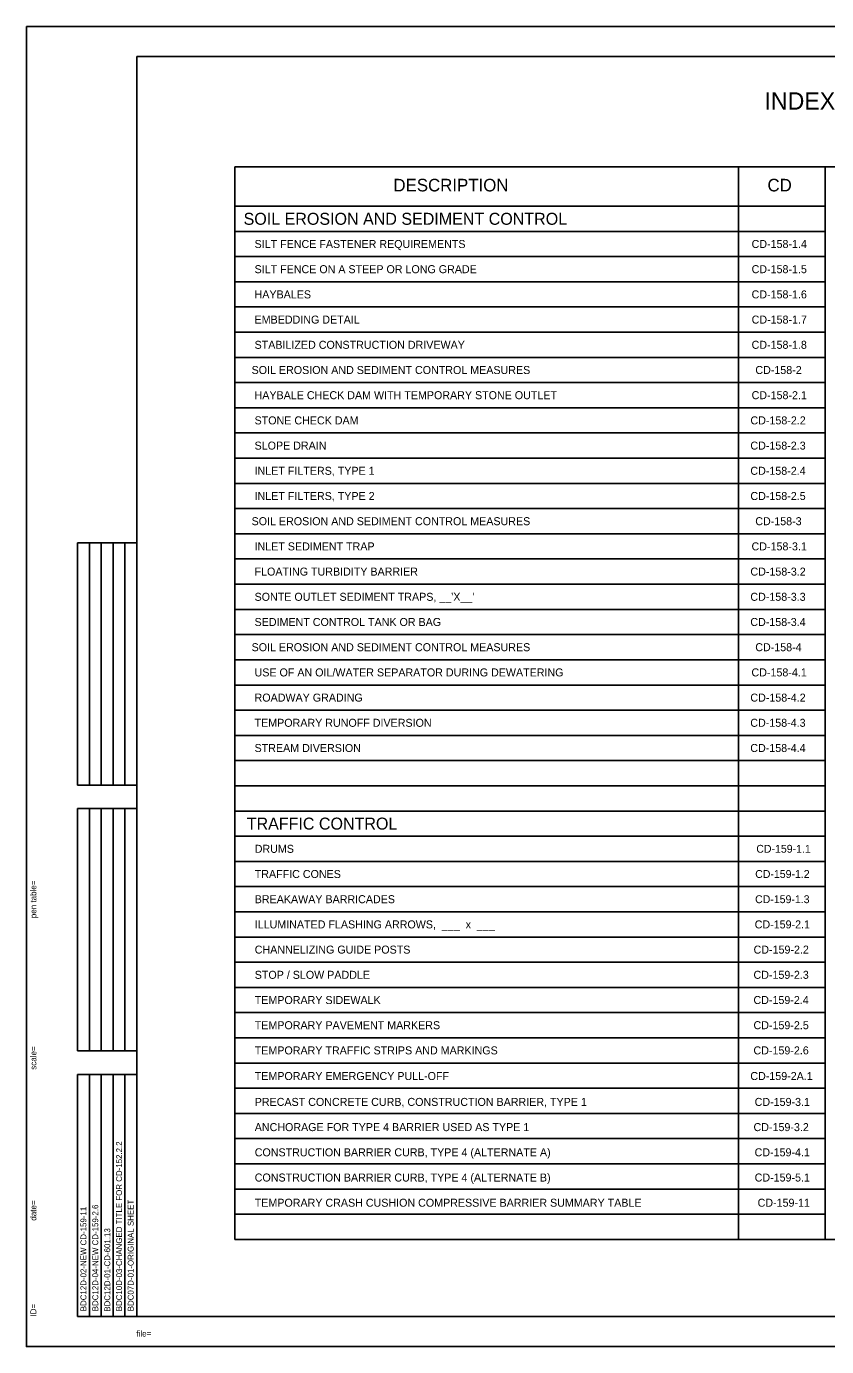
# Model space of a CAD drawing. Extents: x 503613 to 504661, y 499104 to 499764.
# Drawn here: x 503613 to 504013, y 499104 to 499764 of the extents above; entities that cross this region are included whole.
import ezdxf

# ---------------------------------------------------------------- set-up
doc = ezdxf.new("R2010")
doc.units = 0
for name, color, linetype in [('1', 7, 'Continuous'), ('39', 7, 'Continuous'), ('41', 7, 'Continuous')]:
    doc.layers.add(name, color=color, linetype=linetype)

msp = doc.modelspace()

# ---------------------------------------------------------------- linework, layer by layer
at = {"layer": '1'}
for p, q in [((504661.22, 499764.48), (503613.04, 499764.48)), ((504658.22, 499749.48), (503668.22, 499749.48)), ((503668.22, 499749.48), (503668.22, 499119.48)), ((503717.27, 499694.28), (504603.1, 499694.28)), ((503717.27, 499158.06), (503717.27, 499694.28)), ((503717.27, 499674.59), (503717.27, 499694.28)), ((503969.24, 499158.06), (503969.24, 499694.28)), ((503969.24, 499674.59), (503969.24, 499694.28)), ((504012.55, 499158.06), (504012.55, 499694.28)), ((504012.55, 499674.59), (504012.55, 499694.28)), ((503717.27, 499674.59), (504012.55, 499674.59)), ((503717.27, 499662), (504012.55, 499662)), ((503717.27, 499649.4), (504012.55, 499649.4)), ((503717.27, 499636.8), (504012.55, 499636.8)), ((503717.27, 499624.2), (504012.55, 499624.2)), ((503717.27, 499611.6), (504012.55, 499611.6)), ((503717.27, 499599), (504012.55, 499599)), ((503717.27, 499586.41), (504012.55, 499586.41)), ((503717.27, 499573.81), (504012.55, 499573.81)), ((503717.27, 499561.21), (504012.55, 499561.21)), ((503717.27, 499548.61), (504012.55, 499548.61)), ((503717.27, 499536.01), (504012.55, 499536.01)), ((503717.27, 499523.41), (504012.55, 499523.41)), ((503717.27, 499510.82), (504012.55, 499510.82)), ((503638.69, 499506.29), (503668.22, 499506.29)), ((503638.69, 499385.22), (503638.69, 499506.29)), ((503644.59, 499385.22), (503644.59, 499506.29)), ((503650.5, 499385.22), (503650.5, 499506.29)), ((503656.41, 499385.22), (503656.41, 499506.29)), ((503662.31, 499385.22), (503662.31, 499506.29)), ((503717.27, 499498.22), (504012.55, 499498.22)), ((503717.27, 499485.62), (504012.55, 499485.62)), ((503717.27, 499473.02), (504012.55, 499473.02)), ((503717.27, 499460.42), (504012.55, 499460.42)), ((503717.27, 499447.82), (504012.55, 499447.82)), ((503717.27, 499435.22), (504012.55, 499435.22)), ((503717.27, 499422.63), (504012.55, 499422.63)), ((503717.27, 499410.03), (504012.55, 499410.03)), ((503717.27, 499397.43), (504012.55, 499397.43)), ((503668.22, 499385.22), (503638.69, 499385.22)), ((503717.27, 499384.83), (504012.55, 499384.83)), ((503638.69, 499373.41), (503668.22, 499373.41)), ((503638.69, 499252.35), (503638.69, 499373.41)), ((503644.59, 499252.35), (503644.59, 499373.41)), ((503650.5, 499252.35), (503650.5, 499373.41)), ((503656.41, 499252.35), (503656.41, 499373.41)), ((503662.31, 499252.35), (503662.31, 499373.41)), ((503717.27, 499372.23), (504012.55, 499372.23)), ((503717.27, 499359.63), (504012.55, 499359.63)), ((503717.27, 499347.04), (504012.55, 499347.04)), ((503717.27, 499334.44), (504012.55, 499334.44)), ((503717.27, 499321.84), (504012.55, 499321.84)), ((503717.27, 499309.24), (504012.55, 499309.24)), ((503717.27, 499296.64), (504012.55, 499296.64)), ((503717.27, 499284.04), (504012.55, 499284.04)), ((503717.27, 499271.44), (504012.55, 499271.44)), ((503717.27, 499258.85), (504012.55, 499258.85)), ((503668.22, 499252.35), (503638.69, 499252.35)), ((503717.27, 499246.25), (504012.55, 499246.25)), ((503638.69, 499119.48), (503638.69, 499240.54)), ((503638.69, 499240.54), (503668.22, 499240.54)), ((503644.59, 499119.48), (503644.59, 499240.54)), ((503650.5, 499119.48), (503650.5, 499240.54)), ((503656.41, 499119.48), (503656.41, 499240.54)), ((503662.31, 499119.48), (503662.31, 499240.54)), ((503717.27, 499233.65), (504012.55, 499233.65)), ((503717.27, 499221.05), (504012.55, 499221.05)), ((503717.27, 499208.45), (504012.55, 499208.45)), ((503717.27, 499195.85), (504012.55, 499195.85)), ((503717.27, 499183.26), (504012.55, 499183.26)), ((503717.27, 499170.66), (504012.55, 499170.66)), ((503717.27, 499158.06), (504603.1, 499158.06)), ((503717.27, 499158.06), (504012.55, 499158.06)), ((503668.22, 499119.48), (503638.69, 499119.48)), ((503668.22, 499119.48), (504658.22, 499119.48)), ((504661.22, 499104.48), (503613.04, 499104.48))]:
    msp.add_line(p, q, dxfattribs=at)
at = {"layer": '41'}
msp.add_lwpolyline([(503613.04, 499764.48), (504661.22, 499764.48), (504661.22, 499104.48), (503613.04, 499104.48)], close=True, dxfattribs=at)

# ---------------------------------------------------------------- texts
at = {"layer": '1'}
for s, height, p in [('DESCRIPTION', 6.2992, (503796.64, 499681.98)), ('CD', 6.299, (503983.75, 499681.98))]:
    msp.add_text(s, height=height, dxfattribs=at).set_placement(p)
for s, height, rotation, p in [('...................pentable..................', 0.0432, 90, (503618.04, 499342.54)), ('pen table=', 3, 90, (503618.04, 499318.64)), ('......scale......', 0.0432, 90, (503618.04, 499257.54)), ('scale=', 3, 90, (503618.04, 499242.87)), ('.......time......', 0.0432, 90, (503618.04, 499180.54)), ('date=', 3, 90, (503618.04, 499167.41)), ('ID=', 3, 90, (503618.04, 499119.5)), ('............who............', 0.0432, 90, (503618.04, 499127.48)), ('file=', 3, 360, (503668.05, 499109.48)), ('...................bob..................', 0.0432, 360, (503678.04, 499109.48))]:
    msp.add_text(s, height=height, rotation=rotation, dxfattribs=at).set_placement(p)
at = {"layer": '39'}
for s, height, p in [('INDEX FOR STANDARD ROADWAY CONSTRUCTION DETAILS', 8.6614, (503982.24, 499722.87)), ('SOIL EROSION AND SEDIMENT CONTROL ', 6, (503721.7, 499665.29)), (' SILT FENCE FASTENER REQUIREMENTS', 4, (503725.7, 499653.7)), ('CD-158-1.4', 4, (503975.81, 499653.7)), (' SILT FENCE ON A STEEP OR LONG GRADE', 4, (503725.7, 499641.1)), ('CD-158-1.5', 4, (503975.81, 499641.1)), (' HAYBALES', 4, (503725.7, 499628.5)), ('CD-158-1.6', 4, (503975.81, 499628.5)), (' EMBEDDING DETAIL', 4, (503725.7, 499615.9)), ('CD-158-1.7', 4, (503975.83, 499615.9)), (' STABILIZED CONSTRUCTION DRIVEWAY', 4, (503725.7, 499603.3)), ('CD-158-1.8', 4, (503975.81, 499603.3)), ('SOIL EROSION AND SEDIMENT CONTROL MEASURES', 4, (503725.7, 499590.7)), ('CD-158-2', 4, (503977.69, 499590.7)), (' HAYBALE CHECK DAM WITH TEMPORARY STONE OUTLET', 4, (503725.7, 499578.11)), ('CD-158-2.1', 4, (503975.81, 499578.11)), (' STONE CHECK DAM', 4, (503725.7, 499565.51)), ('CD-158-2.2', 4, (503975.24, 499565.51)), (' SLOPE DRAIN', 4, (503725.7, 499552.91)), ('CD-158-2.3', 4, (503975.21, 499552.91)), (' INLET FILTERS, TYPE 1', 4, (503725.7, 499540.31)), ('CD-158-2.4', 4, (503975.2, 499540.31)), (' INLET FILTERS, TYPE 2', 4, (503725.7, 499527.71)), ('CD-158-2.5', 4, (503975.21, 499527.71)), ('SOIL EROSION AND SEDIMENT CONTROL MEASURES', 4, (503725.7, 499515.11)), ('CD-158-3', 4, (503977.65, 499515.11)), (' INLET SEDIMENT TRAP', 4, (503725.7, 499502.52)), ('CD-158-3.1', 4, (503975.79, 499502.52)), (' FLOATING TURBIDITY BARRIER', 4, (503725.7, 499489.92)), ('CD-158-3.2', 4, (503975.22, 499489.92)), (" SONTE OUTLET SEDIMENT TRAPS, __'X__'", 4, (503725.7, 499477.32)), ('CD-158-3.3', 4, (503975.19, 499477.32)), (' SEDIMENT CONTROL TANK OR BAG', 4, (503725.7, 499464.72)), ('CD-158-3.4', 4, (503975.18, 499464.72)), ('SOIL EROSION AND SEDIMENT CONTROL MEASURES', 4, (503725.7, 499452.12)), ('CD-158-4', 4, (503977.65, 499452.12)), (' USE OF AN OIL/WATER SEPARATOR DURING DEWATERING', 4, (503725.7, 499439.52)), ('CD-158-4.1', 4, (503975.76, 499439.52)), (' ROADWAY GRADING', 4, (503725.7, 499426.92)), ('CD-158-4.2', 4, (503975.2, 499426.92)), (' TEMPORARY RUNOFF DIVERSION', 4, (503725.7, 499414.33)), ('CD-158-4.3', 4, (503975.16, 499414.33)), (' STREAM DIVERSION', 4, (503725.7, 499401.73)), ('CD-158-4.4', 4, (503975.16, 499401.73)), ('TRAFFIC CONTROL', 6, (503723.27, 499362.93)), ('DRUMS', 4, (503727.27, 499351.33)), ('CD-159-1.1', 3.937, (503978.17, 499351.37)), ('TRAFFIC CONES', 4, (503727.27, 499338.74)), ('CD-159-1.2', 3.937, (503977.62, 499338.77)), ('BREAKAWAY BARRICADES', 4, (503727.27, 499326.14)), ('CD-159-1.3', 3.937, (503977.58, 499326.17)), ('ILLUMINATED FLASHING ARROWS,  ___  x  ___ ', 4, (503727.27, 499313.54)), ('CD-159-2.1', 4, (503977.36, 499313.54)), ('CHANNELIZING GUIDE POSTS', 4, (503727.27, 499300.94)), ('CD-159-2.2', 4, (503976.8, 499300.94)), ('STOP / SLOW PADDLE', 4, (503727.27, 499288.34)), ('CD-159-2.3', 4, (503976.76, 499288.34)), ('TEMPORARY SIDEWALK', 4, (503727.27, 499275.74)), ('CD-159-2.4', 4, (503976.75, 499275.74)), ('TEMPORARY PAVEMENT MARKERS', 4, (503727.27, 499263.15)), ('CD-159-2.5', 4, (503976.76, 499263.15)), ('TEMPORARY TRAFFIC STRIPS AND MARKINGS', 4, (503727.27, 499250.55)), ('CD-159-2.6', 4, (503976.76, 499250.55)), ('TEMPORARY EMERGENCY PULL-OFF', 4, (503727.27, 499237.74)), ('CD-159-2A.1', 4, (503975.18, 499237.74)), ('PRECAST CONCRETE CURB, CONSTRUCTION BARRIER, TYPE 1', 4, (503727.27, 499224.8)), ('CD-159-3.1', 4, (503977.34, 499224.8)), ('ANCHORAGE FOR TYPE 4 BARRIER USED AS TYPE 1', 4, (503727.27, 499212.2)), ('CD-159-3.2', 4, (503976.78, 499212.2)), ('CONSTRUCTION BARRIER CURB, TYPE 4 (ALTERNATE A)', 4, (503727.27, 499199.6)), ('CD-159-4.1', 4, (503977.32, 499199.6)), ('CONSTRUCTION BARRIER CURB, TYPE 4 (ALTERNATE B)', 4, (503727.27, 499187)), ('CD-159-5.1', 4, (503977.34, 499187)), ('TEMPORARY CRASH CUSHION COMPRESSIVE BARRIER SUMMARY TABLE', 4, (503727.27, 499174.4)), ('CD-159-11', 4, (503978.82, 499174.4))]:
    msp.add_text(s, height=height, dxfattribs=at).set_placement(p)
for s, p in [('BDC10D-03-CHANGED TITLE FOR CD-152.2.2', (503660.89, 499122.15)), ('BDC12D-02-NEW CD-159-11', (503643.06, 499122.15)), ('BDC12D-04-NEW CD-159-2.6', (503648.97, 499122.15)), ('BDC07D-01-ORIGINAL SHEET', (503666.69, 499122.15)), ('BDC12D-01-CD-601.13', (503654.98, 499121.95))]:
    msp.add_text(s, height=2.9528, rotation=90, dxfattribs=at).set_placement(p)

doc.saveas('drawing.dxf')
